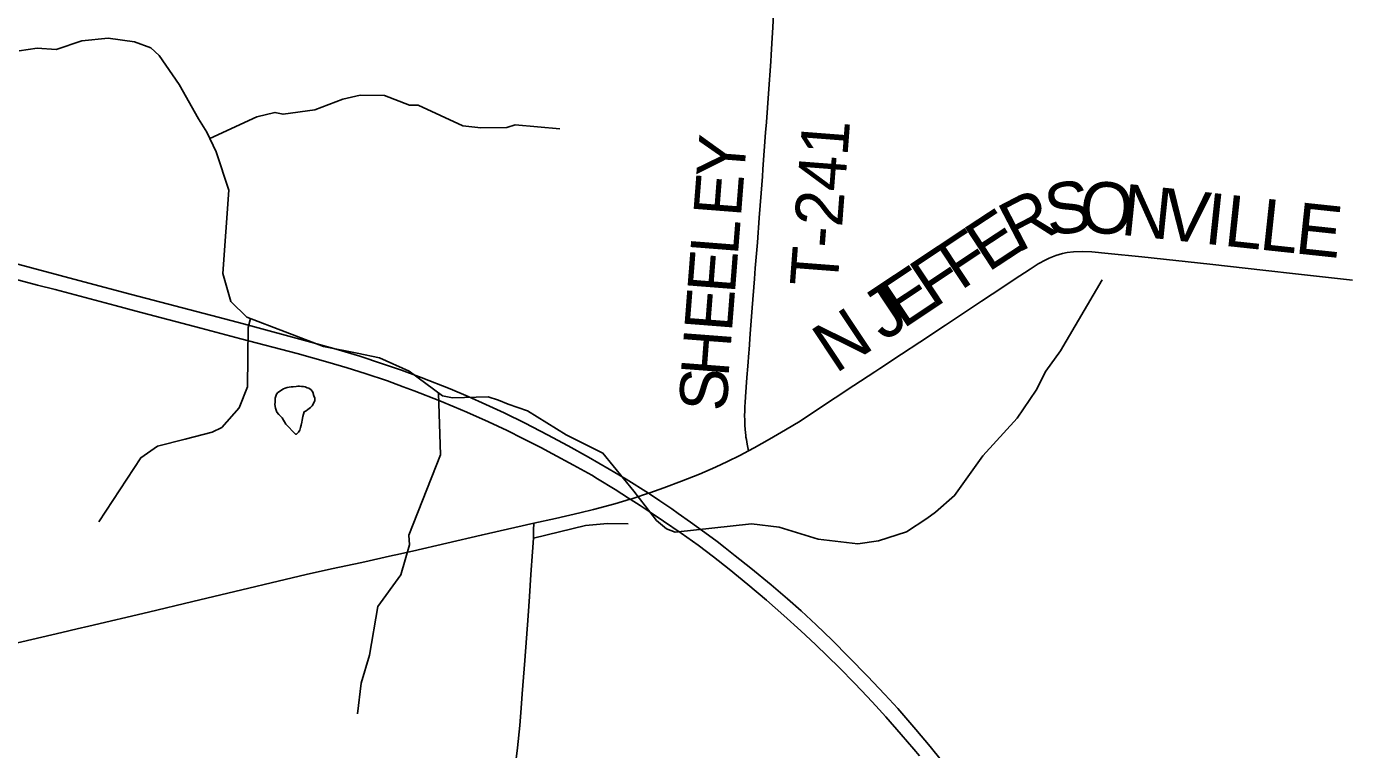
# Model space of a CAD drawing. Extents: x -13.9 to 69.1, y -25.2 to 26.1.
# Drawn here: x 5.08 to 6.483, y 17.826 to 18.591 of the extents above; entities that cross this region are included whole.
import ezdxf

# ---------------------------------------------------------------- set-up
doc = ezdxf.new("R2010")
doc.units = 0
for name, color, linetype in [('GM_X_County_Road', 7, 'Continuous'), ('GM_X_County_Road_Text', 7, 'Continuous'), ('GM_X_Minor_Lake', 7, 'Continuous'), ('GM_X_Minor_River', 7, 'Continuous'), ('GM_X_Township_Road', 7, 'Continuous'), ('GM_X_Township_Road_Text', 7, 'Continuous'), ('GM_X_US_Route', 7, 'Continuous')]:
    doc.layers.add(name, color=color, linetype=linetype)

msp = doc.modelspace()

# ---------------------------------------------------------------- linework, layer by layer
at = {"layer": 'GM_X_County_Road'}
for points in [[(5.9781, 18.2259), (5.9834, 18.2293), (6.0064, 18.2446), (6.0257, 18.2575), (6.053, 18.2754), (6.0911, 18.3007), (6.1138, 18.3157), (6.1255, 18.3235), (6.1425, 18.3347), (6.1511, 18.3401), (6.159, 18.3445), (6.1626, 18.3462), (6.1699, 18.3491), (6.1769, 18.351), (6.1819, 18.3521), (6.1885, 18.353), (6.198, 18.3534), (6.2079, 18.3529), (6.2251, 18.3513), (6.2608, 18.3477), (6.3329, 18.3397), (6.3923, 18.3331), (6.4236, 18.3298), (6.4841, 18.323)], [(5.8443, 18.1423), (5.8504, 18.1455), (5.8666, 18.1545), (5.8836, 18.1644), (5.8989, 18.1738), (5.9164, 18.1852), (5.9559, 18.2114), (5.9781, 18.2259)], [(5.6169, 18.0656), (5.6397, 18.0707), (5.6656, 18.0766), (5.6802, 18.0802), (5.7026, 18.0864), (5.719, 18.0912), (5.7218, 18.092), (5.7384, 18.0974), (5.7398, 18.0978), (5.7545, 18.103), (5.7733, 18.1101), (5.7924, 18.1178), (5.8093, 18.1251), (5.822, 18.1309), (5.835, 18.1374), (5.8443, 18.1423)], [(5.4706, 18.0323), (5.4883, 18.0363), (5.5613, 18.053), (5.5969, 18.0612), (5.6169, 18.0656)], [(5.0642, 17.9378), (5.1171, 17.9501), (5.1333, 17.954), (5.1457, 17.9569), (5.2089, 17.9717), (5.2559, 17.9828), (5.278, 17.988), (5.3757, 18.0113), (5.4028, 18.0173), (5.4347, 18.0242), (5.4672, 18.0315), (5.4706, 18.0323)]]:
    msp.add_lwpolyline(points, dxfattribs=at)
at = {"layer": 'GM_X_Minor_Lake'}
msp.add_lwpolyline([(5.3644, 18.1598), (5.3543, 18.1705), (5.3504, 18.1771), (5.3484, 18.1793), (5.3467, 18.1807), (5.3447, 18.1833), (5.344, 18.1855), (5.3434, 18.1873), (5.3427, 18.1913), (5.3428, 18.1939), (5.3428, 18.1957), (5.3431, 18.1982), (5.3445, 18.2022), (5.3459, 18.204), (5.3476, 18.2051), (5.35, 18.2069), (5.3517, 18.208), (5.3534, 18.2087), (5.3557, 18.2094), (5.3578, 18.2097), (5.3598, 18.21), (5.3622, 18.21), (5.3652, 18.2103), (5.3669, 18.2107), (5.3689, 18.2107), (5.3709, 18.2103), (5.373, 18.2103), (5.3747, 18.2099), (5.377, 18.2091), (5.3787, 18.2087), (5.381, 18.2069), (5.383, 18.2043), (5.384, 18.2007), (5.385, 18.1981), (5.385, 18.1956), (5.3839, 18.193), (5.3822, 18.1901), (5.3805, 18.1883), (5.3775, 18.1862), (5.3758, 18.1848), (5.3737, 18.1837), (5.373, 18.1812), (5.3723, 18.1786), (5.3716, 18.1746), (5.3712, 18.1728), (5.3705, 18.1695), (5.3698, 18.167), (5.3691, 18.1641), (5.3678, 18.1619), (5.3657, 18.1601), (5.3644, 18.1598)], dxfattribs=at)
at = {"layer": 'GM_X_Minor_River'}
for points in [[(5.072, 18.5658), (5.091, 18.5684), (5.1112, 18.5672), (5.1383, 18.5762), (5.166, 18.5789), (5.1939, 18.5751), (5.2113, 18.5689), (5.22, 18.5607), (5.2414, 18.5301), (5.2617, 18.4938), (5.2705, 18.4794), (5.2806, 18.4588), (5.2938, 18.4182), (5.2876, 18.33), (5.2959, 18.3004), (5.3131, 18.2837), (5.3942, 18.2526), (5.4298, 18.2458), (5.4534, 18.2406), (5.4848, 18.2265), (5.5201, 18.2004), (5.5309, 18.1983), (5.5686, 18.1994), (5.5794, 18.1959), (5.5898, 18.1917), (5.6102, 18.1848), (5.6513, 18.1593), (5.69, 18.14), (5.7228, 18.0997), (5.7468, 18.0687), (5.7575, 18.0598), (5.7665, 18.0563), (5.8473, 18.0649), (5.8769, 18.0614), (5.9181, 18.049), (5.9602, 18.0438), (5.9818, 18.047), (6.0116, 18.0566), (6.0331, 18.0707), (6.0423, 18.0774), (6.0625, 18.0949), (6.0925, 18.1372), (6.1289, 18.1768), (6.149, 18.2066), (6.1591, 18.2268), (6.1746, 18.2483), (6.219, 18.3234)], [(5.2738, 18.4727), (5.3234, 18.4958), (5.3427, 18.5005), (5.3514, 18.4985), (5.3849, 18.5033), (5.4147, 18.5144), (5.433, 18.5188), (5.4586, 18.5183), (5.4854, 18.5083), (5.4945, 18.5081), (5.5417, 18.4861), (5.5609, 18.4843), (5.5882, 18.4845), (5.597, 18.4872), (5.6445, 18.483)], [(5.317, 18.2822), (5.3143, 18.2728), (5.3136, 18.2102), (5.3048, 18.1879), (5.2866, 18.1671), (5.2764, 18.1619), (5.2476, 18.1548), (5.2185, 18.1474), (5.2008, 18.135), (5.1562, 18.0672)], [(5.5159, 18.2035), (5.5181, 18.1382), (5.4846, 18.0531), (5.4851, 18.0429), (5.4762, 18.0111), (5.4517, 17.9774), (5.4427, 17.9259), (5.4342, 17.8963), (5.4303, 17.864)]]:
    msp.add_lwpolyline(points, dxfattribs=at)
at = {"layer": 'GM_X_Township_Road'}
for points in [[(5.8689, 18.5735), (5.8699, 18.5906), (5.8713, 18.6179), (5.8719, 18.628), (5.8736, 18.6557)], [(5.8445, 18.2461), (5.8448, 18.2497), (5.8461, 18.2663), (5.8482, 18.2936), (5.8506, 18.3244), (5.8515, 18.3356), (5.8537, 18.3629), (5.8557, 18.389), (5.8577, 18.4151), (5.859, 18.4328), (5.8596, 18.4405), (5.8624, 18.4791), (5.8632, 18.4903), (5.8654, 18.5206), (5.8678, 18.5544), (5.8683, 18.5615), (5.8689, 18.5735)], [(5.8443, 18.1423), (5.843, 18.1493), (5.842, 18.1543), (5.8416, 18.1567), (5.8414, 18.1584), (5.8411, 18.1617), (5.8408, 18.1649), (5.8405, 18.1696), (5.8403, 18.1749), (5.8402, 18.1798), (5.8403, 18.1844), (5.8405, 18.1892), (5.8407, 18.1934), (5.841, 18.1993), (5.8425, 18.2201), (5.8435, 18.2319), (5.8445, 18.2461)], [(5.6123, 17.9883), (5.6139, 18.0116), (5.6154, 18.0354), (5.6166, 18.05), (5.6166, 18.0514), (5.6167, 18.0585), (5.6169, 18.0656)], [(5.6166, 18.05), (5.6718, 18.0632), (5.6948, 18.0655), (5.7167, 18.0651)], [(5.5721, 17.608), (5.5729, 17.6144), (5.5748, 17.6291), (5.578, 17.6569), (5.5817, 17.6863), (5.5838, 17.7023), (5.5875, 17.7311), (5.5913, 17.7618), (5.5944, 17.7854), (5.5995, 17.8279), (5.602, 17.8515), (5.6036, 17.8699), (5.6047, 17.8853), (5.6073, 17.9203), (5.6109, 17.9677), (5.6123, 17.9883)]]:
    msp.add_lwpolyline(points, dxfattribs=at)
at = {"layer": 'GM_X_US_Route'}
for points in [[(5.0598, 18.3427), (5.1403, 18.3212), (5.1907, 18.3078), (5.2826, 18.2837), (5.3094, 18.2767), (5.3807, 18.2575), (5.4075, 18.2499), (5.4325, 18.2424), (5.4568, 18.2345), (5.4768, 18.2276), (5.4977, 18.2199), (5.5283, 18.2078), (5.5473, 18.1998), (5.5662, 18.1915), (5.5855, 18.1825), (5.6076, 18.1716), (5.6315, 18.1593), (5.6533, 18.1477), (5.6749, 18.1356), (5.6968, 18.1229), (5.7146, 18.1122), (5.7384, 18.0974), (5.7394, 18.0967), (5.7503, 18.0895), (5.7629, 18.081), (5.7698, 18.0761), (5.7828, 18.067), (5.802, 18.053), (5.8111, 18.0463), (5.8196, 18.0397), (5.8303, 18.0313), (5.8468, 18.0182), (5.8682, 18.0005), (5.8855, 17.9857), (5.9, 17.9729), (5.916, 17.9581), (5.9328, 17.9419), (5.9507, 17.9241), (5.9703, 17.904), (5.9887, 17.8844), (6.0023, 17.8695), (6.0215, 17.8474), (6.0368, 17.8294), (6.0484, 17.8151)], [(5.0515, 18.3282), (5.0913, 18.3178), (5.1101, 18.313), (5.1734, 18.2963), (5.1959, 18.2901), (5.2641, 18.2722), (5.3065, 18.261), (5.3661, 18.2453), (5.3988, 18.2363), (5.4191, 18.2303), (5.4382, 18.2243), (5.4619, 18.2163), (5.4667, 18.2146), (5.4787, 18.2102), (5.4902, 18.2059), (5.5172, 18.1952), (5.5327, 18.1888), (5.546, 18.1831), (5.569, 18.1729), (5.5787, 18.1684), (5.5888, 18.1637), (5.6054, 18.1555), (5.6144, 18.1509), (5.6244, 18.1457), (5.6368, 18.1393), (5.6591, 18.1273), (5.6782, 18.1165), (5.6845, 18.1127), (5.7032, 18.1013), (5.717, 18.0924), (5.719, 18.0912), (5.7294, 18.0846), (5.7402, 18.0774), (5.7543, 18.068), (5.773, 18.0552), (5.7909, 18.0424), (5.8073, 18.0301), (5.8238, 18.0171), (5.8436, 18.0009), (5.8632, 17.9844), (5.8816, 17.9682), (5.8998, 17.9518), (5.9152, 17.9372), (5.9406, 17.9125), (5.9564, 17.8966), (5.9702, 17.882), (5.9792, 17.8724), (5.9896, 17.8608), (6.0059, 17.8422), (6.0194, 17.8265), (6.0253, 17.8194)]]:
    msp.add_lwpolyline(points, dxfattribs=at)

# ---------------------------------------------------------------- texts
at = {"layer": 'GM_X_County_Road_Text'}
for s, height, rotation, p in [('S', 0.0543, 8.6436, (6.1624, 18.3693)), ('O', 0.0544, 355.702, (6.1934, 18.3744)), ('R', 0.0537, 27.5239, (6.129, 18.3512)), ('N', 0.0543, 354.0717, (6.2374, 18.3711)), ('V', 0.0543, 353.9222, (6.2817, 18.3665)), ('I', 0.0543, 353.9205, (6.3259, 18.3617)), ('L', 0.0543, 353.9205, (6.3466, 18.3595)), ('E', 0.0534, 33.2356, (6.0979, 18.3307)), ('L', 0.0543, 353.9202, (6.3842, 18.3555)), ('E', 0.0543, 353.9245, (6.4218, 18.3515)), ('F', 0.0533, 33.579, (6.0689, 18.3114)), ('F', 0.0533, 33.597, (6.0399, 18.2922)), ('E', 0.0533, 33.5951, (6.0077, 18.2708)), ('J', 0.0533, 33.5947, (5.9875, 18.2574)), ('N', 0.0533, 33.5958, (5.9364, 18.2234))]:
    msp.add_text(s, height=height, rotation=rotation, dxfattribs=at).set_placement(p)
at = {"layer": 'GM_X_Township_Road_Text'}
for s, height, rotation, p in [('T-241', 0.05057, 85.6151, (5.9384, 18.3147)), ('Y', 0.0506, 85.524, (5.8393, 18.4295)), ('E', 0.0506, 85.5294, (5.8362, 18.389)), ('L', 0.0506, 85.524, (5.833, 18.3485)), ('E', 0.0506, 85.5294, (5.8298, 18.3079)), ('E', 0.0506, 85.524, (5.8266, 18.2674)), ('H', 0.0506, 85.6192, (5.823, 18.2197)), ('S', 0.0506, 87.3975, (5.8214, 18.1836))]:
    msp.add_text(s, height=height, rotation=rotation, dxfattribs=at).set_placement(p)

doc.saveas('drawing.dxf')
